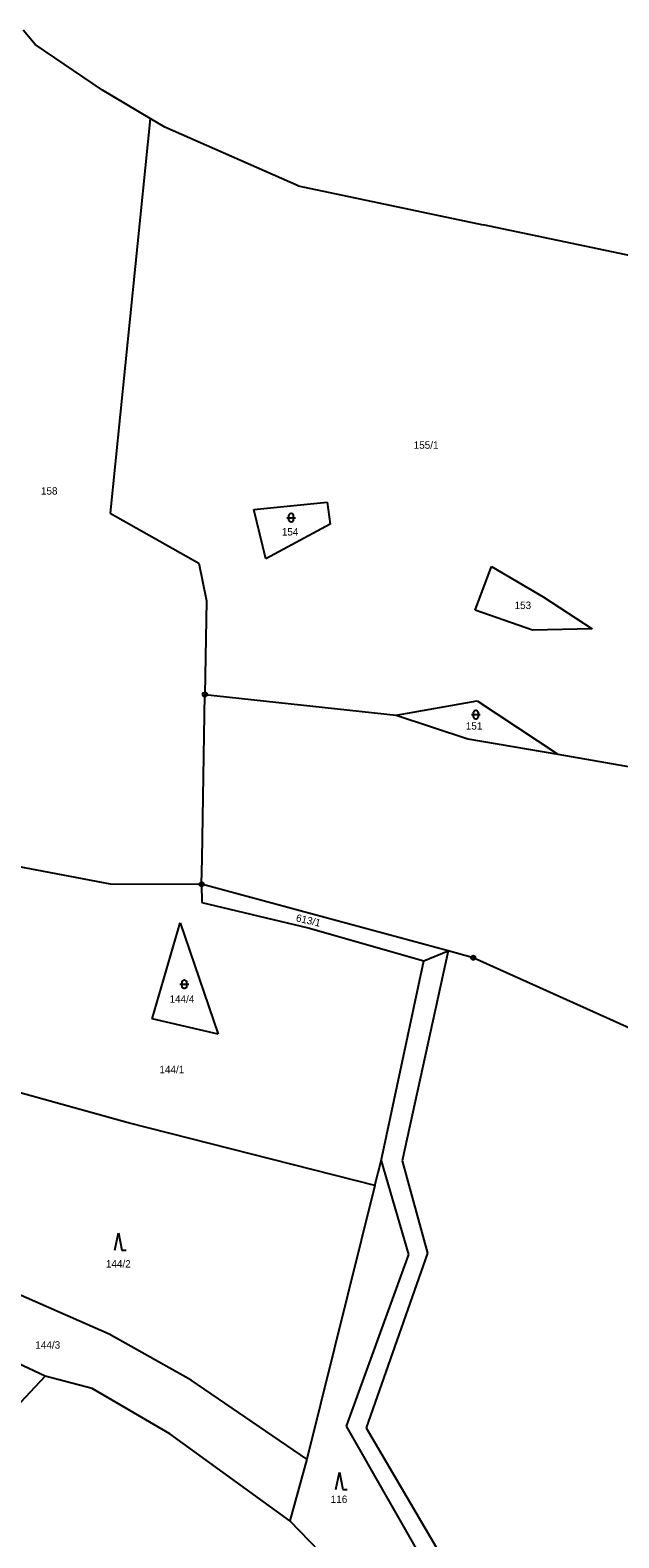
# Model space of a CAD drawing. Extents: x -794421 to -792735, y -1117671 to -1115559.
# Drawn here: x -793325.1 to -793190.4, y -1116417 to -1116072.1 of the extents above; entities that cross this region are included whole.
import ezdxf

# ---------------------------------------------------------------- set-up
doc = ezdxf.new("R2010")
doc.units = 0
for name, color, linetype in [('Vrstva 1', 7, 'Continuous'), ('Vrstva 14', 7, 'Continuous'), ('Vrstva 23', 7, 'Continuous'), ('Vrstva 28', 7, 'Continuous'), ('Vrstva 3', 7, 'Continuous')]:
    doc.layers.add(name, color=color, linetype=linetype)

msp = doc.modelspace()

# ---------------------------------------------------------------- linework, layer by layer
at = {"layer": 'Vrstva 1'}
for p, q in [((-793297.63, -1116092.25), (-793306.74, -1116182.59)), ((-793273.91, -1116181.77), (-793257.09, -1116180.08)), ((-793271.11, -1116192.99), (-793273.91, -1116181.77)), ((-793257.09, -1116180.08), (-793256.39, -1116185.06)), ((-793306.74, -1116182.59), (-793286.46, -1116194.03)), ((-793256.39, -1116185.06), (-793271.11, -1116192.99)), ((-793286.46, -1116194.03), (-793284.71, -1116202.6)), ((-793223.28, -1116204.79), (-793219.49, -1116194.77)), ((-793219.49, -1116194.77), (-793207.69, -1116201.72)), ((-793284.71, -1116202.6), (-793285.09, -1116224.05)), ((-793207.69, -1116201.72), (-793196.5, -1116209.07)), ((-793210.11, -1116209.36), (-793223.28, -1116204.79)), ((-793196.5, -1116209.07), (-793210.11, -1116209.36)), ((-793241.34, -1116228.8), (-793222.82, -1116225.49)), ((-793222.82, -1116225.49), (-793204.36, -1116237.71)), ((-793339.57, -1116261.15), (-793306.78, -1116267.35)), ((-793306.78, -1116267.35), (-793285.84, -1116267.48)), ((-793285.84, -1116267.48), (-793285.82, -1116271.66)), ((-793285.82, -1116271.66), (-793261.43, -1116277.42)), ((-793297.13, -1116298.26), (-793290.75, -1116276.33)), ((-793290.75, -1116276.33), (-793282.02, -1116301.75)), ((-793261.43, -1116277.42), (-793235.03, -1116285)), ((-793244.79, -1116330.78), (-793235.03, -1116285)), ((-793229.44, -1116282.73), (-793239.94, -1116330.77)), ((-793235.03, -1116285), (-793229.44, -1116282.73)), ((-793282.02, -1116301.75), (-793297.13, -1116298.26)), ((-793302.6, -1116322.05), (-793348.29, -1116309.37)), ((-793246.23, -1116336.4), (-793302.6, -1116322.05)), ((-793246.23, -1116336.4), (-793244.79, -1116330.78)), ((-793244.79, -1116330.78), (-793238.52, -1116352.17)), ((-793239.94, -1116330.77), (-793234.18, -1116351.87)), ((-793246.23, -1116336.4), (-793261.77, -1116398.98)), ((-793306.98, -1116370.42), (-793370.56, -1116342.5)), ((-793321.66, -1116379.99), (-793378.31, -1116353.61)), ((-793238.52, -1116352.17), (-793252.79, -1116391.44)), ((-793234.18, -1116351.87), (-793248.18, -1116391.83)), ((-793288.24, -1116380.93), (-793306.98, -1116370.42)), ((-793365.92, -1116427.35), (-793321.66, -1116379.99)), ((-793310.86, -1116382.81), (-793321.66, -1116379.99)), ((-793261.77, -1116398.98), (-793288.24, -1116380.93)), ((-793293.13, -1116393.18), (-793310.86, -1116382.81)), ((-793252.79, -1116391.44), (-793232.07, -1116427.65)), ((-793248.18, -1116391.83), (-793227.16, -1116427.57)), ((-793265.68, -1116413.08), (-793293.13, -1116393.18)), ((-793261.77, -1116398.98), (-793265.68, -1116413.08)), ((-793246.55, -1116432.82), (-793265.68, -1116413.08))]:
    msp.add_line(p, q, dxfattribs=at)
at = {"layer": 'Vrstva 23'}
for p, q in [((-793266.36, -1116183.61), (-793264.36, -1116183.61)), ((-793265.86, -1116183.01), (-793265.76, -1116182.81)), ((-793265.86, -1116184.21), (-793265.86, -1116183.01)), ((-793265.76, -1116184.41), (-793265.86, -1116184.21)), ((-793265.76, -1116182.81), (-793265.66, -1116182.71)), ((-793265.66, -1116184.51), (-793265.76, -1116184.41)), ((-793265.66, -1116182.71), (-793265.46, -1116182.61)), ((-793265.46, -1116184.61), (-793265.66, -1116184.51)), ((-793265.46, -1116182.61), (-793265.26, -1116182.61)), ((-793265.26, -1116184.61), (-793265.46, -1116184.61)), ((-793265.26, -1116182.61), (-793265.06, -1116182.71)), ((-793265.06, -1116184.51), (-793265.26, -1116184.61)), ((-793265.06, -1116182.71), (-793264.96, -1116182.81)), ((-793264.96, -1116184.41), (-793265.06, -1116184.51)), ((-793264.96, -1116182.81), (-793264.86, -1116183.01)), ((-793264.86, -1116184.21), (-793264.96, -1116184.41)), ((-793264.86, -1116183.01), (-793264.86, -1116184.21)), ((-793224.1, -1116228.67), (-793222.1, -1116228.67)), ((-793223.6, -1116228.07), (-793223.5, -1116227.87)), ((-793223.6, -1116229.27), (-793223.6, -1116228.07)), ((-793223.5, -1116229.47), (-793223.6, -1116229.27)), ((-793223.5, -1116227.87), (-793223.4, -1116227.77)), ((-793223.4, -1116229.57), (-793223.5, -1116229.47)), ((-793223.4, -1116227.77), (-793223.2, -1116227.67)), ((-793223.2, -1116229.67), (-793223.4, -1116229.57)), ((-793223.2, -1116227.67), (-793223, -1116227.67)), ((-793223, -1116229.67), (-793223.2, -1116229.67)), ((-793223, -1116227.67), (-793222.8, -1116227.77)), ((-793222.8, -1116229.57), (-793223, -1116229.67)), ((-793222.8, -1116227.77), (-793222.7, -1116227.87)), ((-793222.7, -1116229.47), (-793222.8, -1116229.57)), ((-793222.7, -1116227.87), (-793222.6, -1116228.07)), ((-793222.6, -1116229.27), (-793222.7, -1116229.47)), ((-793222.6, -1116228.07), (-793222.6, -1116229.27)), ((-793290.79, -1116290.36), (-793288.79, -1116290.36)), ((-793290.29, -1116289.76), (-793290.19, -1116289.56)), ((-793290.29, -1116290.96), (-793290.29, -1116289.76)), ((-793290.19, -1116291.16), (-793290.29, -1116290.96)), ((-793290.19, -1116289.56), (-793290.09, -1116289.46)), ((-793290.09, -1116291.26), (-793290.19, -1116291.16)), ((-793290.09, -1116289.46), (-793289.89, -1116289.36)), ((-793289.89, -1116291.36), (-793290.09, -1116291.26)), ((-793289.89, -1116289.36), (-793289.69, -1116289.36)), ((-793289.69, -1116291.36), (-793289.89, -1116291.36)), ((-793289.69, -1116289.36), (-793289.49, -1116289.46)), ((-793289.49, -1116291.26), (-793289.69, -1116291.36)), ((-793289.49, -1116289.46), (-793289.39, -1116289.56)), ((-793289.39, -1116291.16), (-793289.49, -1116291.26)), ((-793289.39, -1116289.56), (-793289.29, -1116289.76)), ((-793289.29, -1116290.96), (-793289.39, -1116291.16)), ((-793289.29, -1116289.76), (-793289.29, -1116290.96)), ((-793305.66, -1116351.21), (-793304.86, -1116347.21)), ((-793304.86, -1116347.21), (-793304.06, -1116351.21)), ((-793304.06, -1116351.21), (-793303.06, -1116351.21)), ((-793255.12, -1116405.98), (-793254.32, -1116401.98)), ((-793254.32, -1116401.98), (-793253.52, -1116405.98)), ((-793253.52, -1116405.98), (-793252.52, -1116405.98))]:
    msp.add_line(p, q, dxfattribs=at)
at = {"layer": 'Vrstva 28'}
for centre, radius in [((-793285.09, -1116224.05), 0.5), ((-793285.09, -1116224.05), 0.01), ((-793285.84, -1116267.48), 0.5), ((-793285.84, -1116267.48), 0.01), ((-793223.68, -1116284.29), 0.5), ((-793223.68, -1116284.29), 0.01)]:
    msp.add_circle(centre, radius, dxfattribs=at)
at = {"layer": 'Vrstva 3'}
for p, q in [((-793323.93, -1116075.39), (-793326.69, -1116072.07)), ((-793308.52, -1116085.78), (-793323.93, -1116075.39)), ((-793297.63, -1116092.25), (-793308.52, -1116085.78)), ((-793294.23, -1116094.27), (-793297.63, -1116092.25)), ((-793263.77, -1116107.72), (-793294.23, -1116094.27)), ((-793263.77, -1116107.72), (-793221.43, -1116116.61)), ((-793181.58, -1116125), (-793221.43, -1116116.61)), ((-793285.74, -1116261.56), (-793285.09, -1116224.05)), ((-793285.09, -1116224.05), (-793241.34, -1116228.8)), ((-793241.34, -1116228.8), (-793224.89, -1116234.21)), ((-793224.89, -1116234.21), (-793204.36, -1116237.71)), ((-793204.36, -1116237.71), (-793170.87, -1116243.6)), ((-793285.84, -1116267.48), (-793285.74, -1116261.56)), ((-793229.44, -1116282.73), (-793285.84, -1116267.48)), ((-793223.68, -1116284.29), (-793229.44, -1116282.73)), ((-793166.01, -1116310.36), (-793223.68, -1116284.29))]:
    msp.add_line(p, q, dxfattribs=at)

# ---------------------------------------------------------------- texts
at = {"layer": 'Vrstva 14'}
for s, p in [('155/1', (-793237.319, -1116167.84)), ('158', (-793322.596, -1116178.33)), ('154', (-793267.482, -1116187.69)), ('153', (-793214.236, -1116204.5)), ('151', (-793225.399, -1116232.1)), ('144/4', (-793293.181, -1116294.59)), ('144/1', (-793295.488, -1116310.7)), ('144/2', (-793307.735, -1116355.17)), ('144/3', (-793323.875, -1116373.72)), ('116', (-793256.293, -1116409.02))]:
    msp.add_text(s, height=1.7, dxfattribs=at).set_placement(p)
msp.add_text('613/1', height=1.7, rotation=346.90446, dxfattribs=at).set_placement((-793264.357, -1116275.921))

doc.saveas('drawing.dxf')
